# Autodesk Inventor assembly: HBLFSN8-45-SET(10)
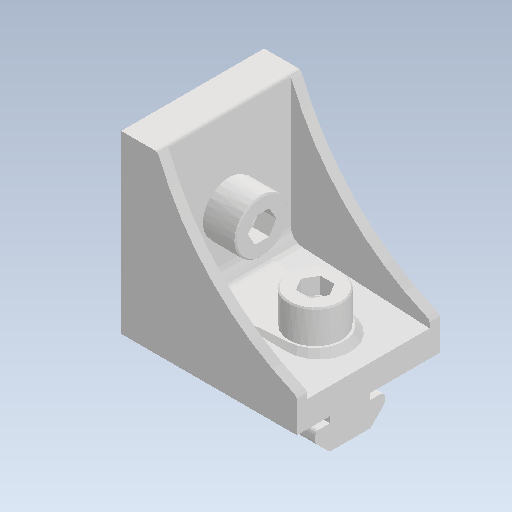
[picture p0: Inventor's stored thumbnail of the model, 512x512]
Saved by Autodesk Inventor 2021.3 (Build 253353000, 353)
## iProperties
Created: 2022-02
Part Number: HBLFSN8-45-SET(10)
Document SubType Name: Assembly
Designer: kengo
Author: kengo
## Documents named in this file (4)
- C:\Users\kengo\Documents\S2S_frame\SDC345\frame_misumi_ver12\HBLFSN8-45-SET(10).iam
- C:\Users\kengo\Documents\S2S_frame\SDC345\frame_misumi_ver12\HBLFSN8-45.ipt
- C:\Users\kengo\Documents\S2S_frame\SDC345\frame_misumi_ver12\HNTT8-8.ipt
- C:\Users\kengo\Documents\S2S_frame\SDC345\frame_misumi_ver12\CBM8-20.ipt
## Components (5 placed, 3 different names)
1. HBLFSN8-45
2. HNTT8-8
3. CBM8-20
4. HNTT8-8:1
5. CBM8-20:1
